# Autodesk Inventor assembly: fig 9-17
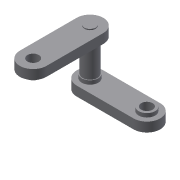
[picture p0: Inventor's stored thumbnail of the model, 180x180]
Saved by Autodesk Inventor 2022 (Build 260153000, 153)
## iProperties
Created: 2002-01
Part Number: fig 9-17
Document SubType Name: Assembly
Designer: ***
Control State: 0
Master: False
Checked Out: False
Shininess: 64.0
Length Units: 11269
Angle Units: 11279
Time Units: 11290
Mass Units: 11283
Length Display Precision: 3
Angle Display Precision: 2
Density: 0.0
Volumn: 0.0
Area: 0.0
PropertySet Name: Model Information
Author: ***
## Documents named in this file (3)
- D:\PROJECTS_2021\Resources\Part Files\c09_Inv_2022_prt\fig 9-17.iam
- D:\PROJECTS_2021\Resources\Part Files\c09_Inv_2022_prt\Part5.ipt
- D:\PROJECTS_2021\Resources\Part Files\c09_Inv_2022_prt\Part6.ipt
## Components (3 placed, 2 different names)
1. Part5:1 — Insert:1
2. Part6:1 — Insert:1, Insert:2
3. Part5:2 — Insert:2
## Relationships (2: Insert 2)
- Insert:1: Part5:1 ↔ Part6:1
- Insert:2: Part6:1 ↔ Part5:2
